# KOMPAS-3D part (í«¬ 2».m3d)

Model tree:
1. Эскиз:1
2. Операция выдавливания:1
     Расстояние 1 = 2
3. Эскиз:2
4. Операция выдавливания:2
     Расстояние 1 = 5
5. Эскиз:3
6. Операция выдавливания:3
     Расстояние 1 = 2
7. Эскиз:4
8. Операция выдавливания:4
     Расстояние 1 = 60
9. Эскиз:5
10. Операция выдавливания:5
     Расстояние 1 = 2
11. Эскиз:6
12. Операция выдавливания:6
     Расстояние 1 = 4.5
13. Эскиз:7
14. Операция выдавливания:7
     Расстояние 1 = 2
15. Скругление:1
     Радиус = 1
16. Скругление:2
     Радиус = 1
17. Эскиз:8
18. Вырезать элемент выдавливания:1
     Расстояние 1 = 10; Угол 1 = 35
19. Эскиз:9
20. Вырезать элемент выдавливания:2
     Расстояние 1 = 10; Угол 1 = 35
21. Эскиз:10
22. Вырезать элемент выдавливания:3
     Расстояние 2 = 22; Расстояние 1 = 22; Угол 1 = 35
23. Эскиз:11
24. Вырезать элемент выдавливания:4
     Расстояние 2 = 2; Расстояние 1 = 2
25. Эскиз:12
26. Вырезать элемент выдавливания:5
     Расстояние 2 = 2; Расстояние 1 = 2; Угол 1 = 35
27. Эскиз:13
28. Вырезать элемент выдавливания:6
     Расстояние 2 = 2; Расстояние 1 = 122
29. Эскиз:15
30. Операция выдавливания:9
     Расстояние 1 = 10; Расстояние 2 = 0.5
